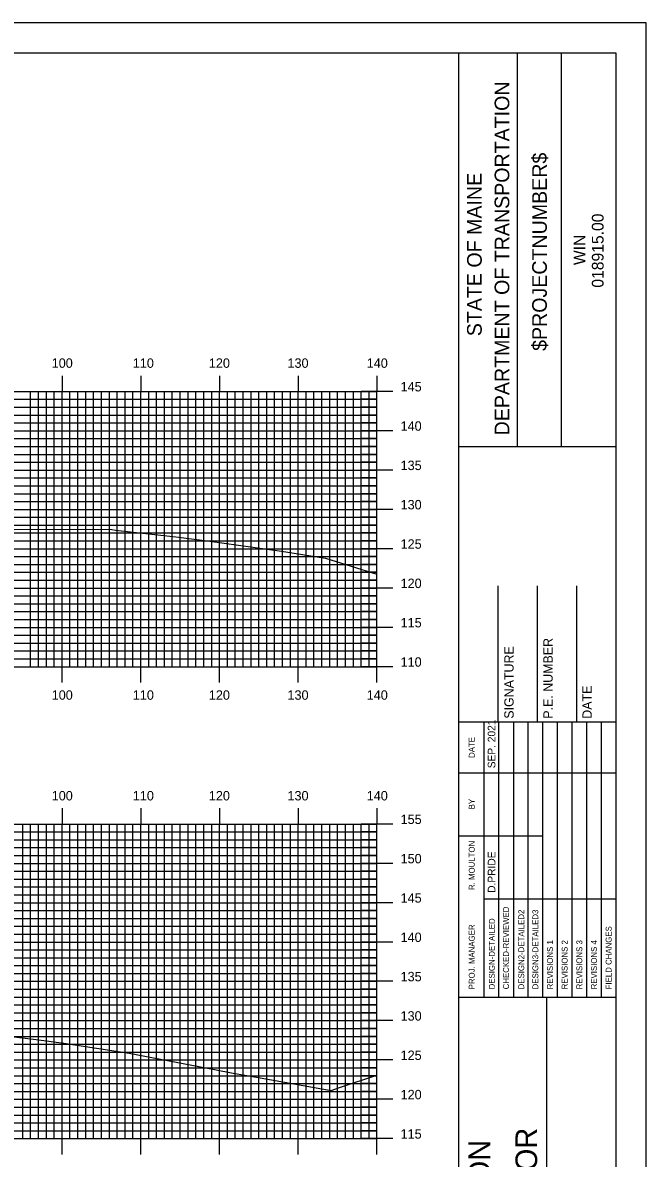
# Model space of a CAD drawing. Extents: x 852320 to 852663, y 366605 to 366825.
# Drawn here: x 852580.5 to 852659.7, y 366680.6 to 366824.9 of the extents above; entities that cross this region are included whole.
import ezdxf

# ---------------------------------------------------------------- set-up
doc = ezdxf.new("R2010")
doc.units = 0
for name, color, linetype in [('BORDER', 7, 'Continuous'), ('H_V ANNOTATION', 7, 'Continuous'), ('MAJOR', 7, 'Continuous'), ('MINOR', 7, 'Continuous'), ('PLOT BOUNDARY', 7, 'Continuous'), ('S_Roadway_Centerline', 7, 'Continuous')]:
    doc.layers.add(name, color=color, linetype=linetype)

msp = doc.modelspace()

# ---------------------------------------------------------------- linework, layer by layer
at = {"layer": 'BORDER'}
for p, q in [((852635.88, 366611.06), (852635.88, 366821.06)), ((852643.33, 366771.05), (852643.33, 366821.05)), ((852648.92, 366771.05), (852648.92, 366821.05)), ((852635.88, 366771.04), (852655.88, 366771.04)), ((852640.88, 366736.06), (852640.88, 366753.36)), ((852645.88, 366736.06), (852645.88, 366753.36)), ((852650.88, 366736.06), (852650.88, 366753.36)), ((852635.88, 366736.06), (852655.88, 366736.06)), ((852635.88, 366701.06), (852655.88, 366701.06)), ((852647.06, 366631.06), (852647.06, 366701.06))]:
    msp.add_line(p, q, dxfattribs=at)
msp.add_lwpolyline([(852335.88, 366611.06), (852655.88, 366611.06), (852655.88, 366821.06), (852335.88, 366821.06)], close=True, dxfattribs=at)
for points in [[(852639.11, 366729.56), (852639.11, 366736.06)], [(852640.97, 366701.07), (852640.97, 366736.06)], [(852642.84, 366736.06), (852642.84, 366701.07)], [(852644.7, 366701.07), (852644.7, 366736.06)], [(852646.56, 366701.07), (852646.56, 366736.06)], [(852648.43, 366701.07), (852648.43, 366736.06)], [(852650.29, 366701.07), (852650.29, 366736.06)], [(852652.15, 366701.07), (852652.15, 366736.06)], [(852654.02, 366701.07), (852654.02, 366736.06)], [(852639.11, 366701.07), (852639.11, 366734.65)], [(852635.88, 366729.56), (852655.88, 366729.56)], [(852635.88, 366721.56), (852639.11, 366721.56)], [(852639.11, 366721.56), (852646.56, 366721.56)], [(852639.11, 366713.56), (852655.88, 366713.56)]]:
    msp.add_lwpolyline(points, dxfattribs=at)
at = {"layer": 'MAJOR'}
for p, q in [((852585.48, 366780.06), (852585.48, 366778.06)), ((852595.48, 366780.06), (852595.48, 366778.06)), ((852605.48, 366780.06), (852605.48, 366778.06)), ((852615.48, 366780.06), (852615.48, 366778.06)), ((852625.48, 366780.06), (852625.48, 366778.06)), ((852345.48, 366778.06), (852625.48, 366778.06)), ((852345.48, 366778.06), (852625.48, 366778.06)), ((852585.48, 366743.06), (852585.48, 366778.06)), ((852595.48, 366743.06), (852595.48, 366778.06)), ((852605.48, 366743.06), (852605.48, 366778.06)), ((852615.48, 366743.06), (852615.48, 366778.06)), ((852627.48, 366778.06), (852623.47, 366778.06)), ((852625.48, 366743.06), (852625.48, 366778.06)), ((852625.48, 366743.06), (852625.48, 366778.06)), ((852345.48, 366773.06), (852625.48, 366773.06)), ((852627.48, 366773.06), (852623.47, 366773.06)), ((852345.48, 366768.06), (852625.48, 366768.06)), ((852627.48, 366768.06), (852623.47, 366768.06)), ((852345.48, 366763.06), (852625.48, 366763.06)), ((852627.48, 366763.06), (852623.47, 366763.06)), ((852345.48, 366758.06), (852625.48, 366758.06)), ((852627.48, 366758.06), (852623.47, 366758.06)), ((852345.48, 366753.06), (852625.48, 366753.06)), ((852627.48, 366753.06), (852623.47, 366753.06)), ((852345.48, 366748.06), (852625.48, 366748.06)), ((852627.48, 366748.06), (852623.47, 366748.06)), ((852345.48, 366743.06), (852625.48, 366743.06)), ((852345.48, 366743.06), (852625.48, 366743.06)), ((852585.48, 366741.05), (852585.48, 366743.06)), ((852595.48, 366741.05), (852595.48, 366743.06)), ((852605.48, 366741.05), (852605.48, 366743.06)), ((852615.48, 366741.05), (852615.48, 366743.06)), ((852627.48, 366743.06), (852623.47, 366743.06)), ((852625.48, 366741.05), (852625.48, 366743.06)), ((852585.48, 366725.06), (852585.48, 366723.06)), ((852595.48, 366725.06), (852595.48, 366723.06)), ((852605.48, 366725.06), (852605.48, 366723.06)), ((852615.48, 366725.06), (852615.48, 366723.06)), ((852625.48, 366725.06), (852625.48, 366723.06)), ((852345.48, 366723.06), (852625.48, 366723.06)), ((852345.48, 366723.06), (852625.48, 366723.06)), ((852585.48, 366683.06), (852585.48, 366723.06)), ((852595.48, 366683.06), (852595.48, 366723.06)), ((852605.48, 366683.06), (852605.48, 366723.06)), ((852615.48, 366683.06), (852615.48, 366723.06)), ((852627.48, 366723.06), (852623.47, 366723.06)), ((852625.48, 366683.06), (852625.48, 366723.06)), ((852625.48, 366683.06), (852625.48, 366723.06)), ((852345.48, 366718.06), (852625.48, 366718.06)), ((852627.48, 366718.06), (852623.47, 366718.06)), ((852345.48, 366713.06), (852625.48, 366713.06)), ((852627.48, 366713.06), (852623.47, 366713.06)), ((852345.48, 366708.06), (852625.48, 366708.06)), ((852627.48, 366708.06), (852623.47, 366708.06)), ((852345.48, 366703.06), (852625.48, 366703.06)), ((852627.48, 366703.06), (852623.47, 366703.06)), ((852345.48, 366698.06), (852625.48, 366698.06)), ((852627.48, 366698.06), (852623.47, 366698.06)), ((852345.48, 366693.06), (852625.48, 366693.06)), ((852627.48, 366693.06), (852623.47, 366693.06)), ((852345.48, 366688.06), (852625.48, 366688.06)), ((852627.48, 366688.06), (852623.47, 366688.06)), ((852345.48, 366683.06), (852625.48, 366683.06)), ((852345.48, 366683.06), (852625.48, 366683.06)), ((852585.48, 366681.05), (852585.48, 366683.06)), ((852595.48, 366681.05), (852595.48, 366683.06)), ((852605.48, 366681.05), (852605.48, 366683.06)), ((852615.48, 366681.05), (852615.48, 366683.06)), ((852627.48, 366683.06), (852623.47, 366683.06)), ((852625.48, 366681.05), (852625.48, 366683.06))]:
    msp.add_line(p, q, dxfattribs=at)
at = {"layer": 'MINOR'}
for p, q in [((852345.48, 366777.06), (852625.48, 366777.06)), ((852581.48, 366743.06), (852581.48, 366778.06)), ((852582.48, 366743.06), (852582.48, 366778.06)), ((852583.48, 366743.06), (852583.48, 366778.06)), ((852584.48, 366743.06), (852584.48, 366778.06)), ((852586.48, 366743.06), (852586.48, 366778.06)), ((852587.48, 366743.06), (852587.48, 366778.06)), ((852588.48, 366743.06), (852588.48, 366778.06)), ((852589.48, 366743.06), (852589.48, 366778.06)), ((852590.48, 366743.06), (852590.48, 366778.06)), ((852591.48, 366743.06), (852591.48, 366778.06)), ((852592.48, 366743.06), (852592.48, 366778.06)), ((852593.48, 366743.06), (852593.48, 366778.06)), ((852594.48, 366743.06), (852594.48, 366778.06)), ((852596.48, 366743.06), (852596.48, 366778.06)), ((852597.48, 366743.06), (852597.48, 366778.06)), ((852598.48, 366743.06), (852598.48, 366778.06)), ((852599.48, 366743.06), (852599.48, 366778.06)), ((852600.48, 366743.06), (852600.48, 366778.06)), ((852601.48, 366743.06), (852601.48, 366778.06)), ((852602.48, 366743.06), (852602.48, 366778.06)), ((852603.48, 366743.06), (852603.48, 366778.06)), ((852604.48, 366743.06), (852604.48, 366778.06)), ((852606.48, 366743.06), (852606.48, 366778.06)), ((852607.48, 366743.06), (852607.48, 366778.06)), ((852608.48, 366743.06), (852608.48, 366778.06)), ((852609.48, 366743.06), (852609.48, 366778.06)), ((852610.48, 366743.06), (852610.48, 366778.06)), ((852611.48, 366743.06), (852611.48, 366778.06)), ((852612.48, 366743.06), (852612.48, 366778.06)), ((852613.48, 366743.06), (852613.48, 366778.06)), ((852614.48, 366743.06), (852614.48, 366778.06)), ((852616.48, 366743.06), (852616.48, 366778.06)), ((852617.48, 366743.06), (852617.48, 366778.06)), ((852618.48, 366743.06), (852618.48, 366778.06)), ((852619.48, 366743.06), (852619.48, 366778.06)), ((852620.48, 366743.06), (852620.48, 366778.06)), ((852621.48, 366743.06), (852621.48, 366778.06)), ((852622.48, 366743.06), (852622.48, 366778.06)), ((852625.48, 366777.06), (852623.47, 366777.06)), ((852623.48, 366743.06), (852623.48, 366778.06)), ((852624.48, 366743.06), (852624.48, 366778.06)), ((852345.48, 366776.06), (852625.48, 366776.06)), ((852625.48, 366776.06), (852623.47, 366776.06)), ((852345.48, 366775.06), (852625.48, 366775.06)), ((852345.48, 366774.06), (852625.48, 366774.06)), ((852625.48, 366775.06), (852623.47, 366775.06)), ((852625.48, 366774.06), (852623.47, 366774.06)), ((852345.48, 366772.06), (852625.48, 366772.06)), ((852625.48, 366772.06), (852623.47, 366772.06)), ((852345.48, 366771.06), (852625.48, 366771.06)), ((852345.48, 366770.06), (852625.48, 366770.06)), ((852625.48, 366771.06), (852623.47, 366771.06)), ((852625.48, 366770.06), (852623.47, 366770.06)), ((852345.48, 366769.06), (852625.48, 366769.06)), ((852625.48, 366769.06), (852623.47, 366769.06)), ((852345.48, 366767.06), (852625.48, 366767.06)), ((852625.48, 366767.06), (852623.47, 366767.06)), ((852345.48, 366766.06), (852625.48, 366766.06)), ((852625.48, 366766.06), (852623.47, 366766.06)), ((852345.48, 366765.06), (852625.48, 366765.06)), ((852345.48, 366764.06), (852625.48, 366764.06)), ((852625.48, 366765.06), (852623.47, 366765.06)), ((852625.48, 366764.06), (852623.47, 366764.06)), ((852345.48, 366762.06), (852625.48, 366762.06)), ((852345.48, 366761.06), (852625.48, 366761.06)), ((852625.48, 366762.06), (852623.47, 366762.06)), ((852625.48, 366761.06), (852623.47, 366761.06)), ((852345.48, 366760.06), (852625.48, 366760.06)), ((852625.48, 366760.06), (852623.47, 366760.06)), ((852345.48, 366759.06), (852625.48, 366759.06)), ((852625.48, 366759.06), (852623.47, 366759.06)), ((852345.48, 366757.06), (852625.48, 366757.06)), ((852625.48, 366757.06), (852623.47, 366757.06)), ((852345.48, 366756.06), (852625.48, 366756.06)), ((852625.48, 366756.06), (852623.47, 366756.06)), ((852345.48, 366755.06), (852625.48, 366755.06)), ((852345.48, 366754.06), (852625.48, 366754.06)), ((852625.48, 366755.06), (852623.47, 366755.06)), ((852625.48, 366754.06), (852623.47, 366754.06)), ((852345.48, 366752.06), (852625.48, 366752.06)), ((852345.48, 366751.06), (852625.48, 366751.06)), ((852625.48, 366752.06), (852623.47, 366752.06)), ((852625.48, 366751.06), (852623.47, 366751.06)), ((852345.48, 366750.06), (852625.48, 366750.06)), ((852625.48, 366750.06), (852623.47, 366750.06)), ((852345.48, 366749.06), (852625.48, 366749.06)), ((852625.48, 366749.06), (852623.47, 366749.06)), ((852345.48, 366747.06), (852625.48, 366747.06)), ((852625.48, 366747.06), (852623.47, 366747.06)), ((852345.48, 366746.06), (852625.48, 366746.06)), ((852625.48, 366746.06), (852623.47, 366746.06)), ((852345.48, 366745.06), (852625.48, 366745.06)), ((852345.48, 366744.06), (852625.48, 366744.06)), ((852625.48, 366745.06), (852623.47, 366745.06)), ((852625.48, 366744.06), (852623.47, 366744.06)), ((852345.48, 366722.06), (852625.48, 366722.06)), ((852580.48, 366683.06), (852580.48, 366723.06)), ((852581.48, 366683.06), (852581.48, 366723.06)), ((852582.48, 366683.06), (852582.48, 366723.06)), ((852583.48, 366683.06), (852583.48, 366723.06)), ((852584.48, 366683.06), (852584.48, 366723.06)), ((852586.48, 366683.06), (852586.48, 366723.06)), ((852587.48, 366683.06), (852587.48, 366723.06)), ((852588.48, 366683.06), (852588.48, 366723.06)), ((852589.48, 366683.06), (852589.48, 366723.06)), ((852590.48, 366683.06), (852590.48, 366723.06)), ((852591.48, 366683.06), (852591.48, 366723.06)), ((852592.48, 366683.06), (852592.48, 366723.06)), ((852593.48, 366683.06), (852593.48, 366723.06)), ((852594.48, 366683.06), (852594.48, 366723.06)), ((852596.48, 366683.06), (852596.48, 366723.06)), ((852597.48, 366683.06), (852597.48, 366723.06)), ((852598.48, 366683.06), (852598.48, 366723.06)), ((852599.48, 366683.06), (852599.48, 366723.06)), ((852600.48, 366683.06), (852600.48, 366723.06)), ((852601.48, 366683.06), (852601.48, 366723.06)), ((852602.48, 366683.06), (852602.48, 366723.06)), ((852603.48, 366683.06), (852603.48, 366723.06)), ((852604.48, 366683.06), (852604.48, 366723.06)), ((852606.48, 366683.06), (852606.48, 366723.06)), ((852607.48, 366683.06), (852607.48, 366723.06)), ((852608.48, 366683.06), (852608.48, 366723.06)), ((852609.48, 366683.06), (852609.48, 366723.06)), ((852610.48, 366683.06), (852610.48, 366723.06)), ((852611.48, 366683.06), (852611.48, 366723.06)), ((852612.48, 366683.06), (852612.48, 366723.06)), ((852613.48, 366683.06), (852613.48, 366723.06)), ((852614.48, 366683.06), (852614.48, 366723.06)), ((852616.48, 366683.06), (852616.48, 366723.06)), ((852617.48, 366683.06), (852617.48, 366723.06)), ((852618.48, 366683.06), (852618.48, 366723.06)), ((852619.48, 366683.06), (852619.48, 366723.06)), ((852620.48, 366683.06), (852620.48, 366723.06)), ((852621.48, 366683.06), (852621.48, 366723.06)), ((852622.48, 366683.06), (852622.48, 366723.06)), ((852625.48, 366722.06), (852623.47, 366722.06)), ((852623.48, 366683.06), (852623.48, 366723.06)), ((852624.48, 366683.06), (852624.48, 366723.06)), ((852345.48, 366721.06), (852625.48, 366721.06)), ((852625.48, 366721.06), (852623.47, 366721.06)), ((852345.48, 366720.06), (852625.48, 366720.06)), ((852625.48, 366720.06), (852623.47, 366720.06)), ((852345.48, 366719.06), (852625.48, 366719.06)), ((852625.48, 366719.06), (852623.47, 366719.06)), ((852345.48, 366717.06), (852625.48, 366717.06)), ((852625.48, 366717.06), (852623.47, 366717.06)), ((852345.48, 366716.06), (852625.48, 366716.06)), ((852345.48, 366715.06), (852625.48, 366715.06)), ((852625.48, 366716.06), (852623.47, 366716.06)), ((852625.48, 366715.06), (852623.47, 366715.06)), ((852345.48, 366714.06), (852625.48, 366714.06)), ((852625.48, 366714.06), (852623.47, 366714.06)), ((852345.48, 366712.06), (852625.48, 366712.06)), ((852625.48, 366712.06), (852623.47, 366712.06)), ((852345.48, 366711.06), (852625.48, 366711.06)), ((852625.48, 366711.06), (852623.47, 366711.06)), ((852345.48, 366710.06), (852625.48, 366710.06)), ((852345.48, 366709.06), (852625.48, 366709.06)), ((852625.48, 366710.06), (852623.47, 366710.06)), ((852625.48, 366709.06), (852623.47, 366709.06)), ((852345.48, 366707.06), (852625.48, 366707.06)), ((852625.48, 366707.06), (852623.47, 366707.06)), ((852345.48, 366706.06), (852625.48, 366706.06)), ((852345.48, 366705.06), (852625.48, 366705.06)), ((852625.48, 366706.06), (852623.47, 366706.06)), ((852625.48, 366705.06), (852623.47, 366705.06)), ((852345.48, 366704.06), (852625.48, 366704.06)), ((852625.48, 366704.06), (852623.47, 366704.06)), ((852345.48, 366702.06), (852625.48, 366702.06)), ((852625.48, 366702.06), (852623.47, 366702.06)), ((852345.48, 366701.06), (852625.48, 366701.06)), ((852625.48, 366701.06), (852623.47, 366701.06)), ((852345.48, 366700.06), (852625.48, 366700.06)), ((852345.48, 366699.06), (852625.48, 366699.06)), ((852625.48, 366700.06), (852623.47, 366700.06)), ((852625.48, 366699.06), (852623.47, 366699.06)), ((852345.48, 366697.06), (852625.48, 366697.06)), ((852345.48, 366696.06), (852625.48, 366696.06)), ((852625.48, 366697.06), (852623.47, 366697.06)), ((852625.48, 366696.06), (852623.47, 366696.06)), ((852345.48, 366695.06), (852625.48, 366695.06)), ((852625.48, 366695.06), (852623.47, 366695.06)), ((852345.48, 366694.06), (852625.48, 366694.06)), ((852625.48, 366694.06), (852623.47, 366694.06)), ((852345.48, 366692.06), (852625.48, 366692.06)), ((852625.48, 366692.06), (852623.47, 366692.06)), ((852345.48, 366691.06), (852625.48, 366691.06)), ((852625.48, 366691.06), (852623.47, 366691.06)), ((852345.48, 366690.06), (852625.48, 366690.06)), ((852345.48, 366689.06), (852625.48, 366689.06)), ((852625.48, 366690.06), (852623.47, 366690.06)), ((852625.48, 366689.06), (852623.47, 366689.06)), ((852345.48, 366687.06), (852625.48, 366687.06)), ((852345.48, 366686.06), (852625.48, 366686.06)), ((852625.48, 366687.06), (852623.47, 366687.06)), ((852625.48, 366686.06), (852623.47, 366686.06)), ((852345.48, 366685.06), (852625.48, 366685.06)), ((852625.48, 366685.06), (852623.47, 366685.06)), ((852345.48, 366684.06), (852625.48, 366684.06)), ((852625.48, 366684.06), (852623.47, 366684.06))]:
    msp.add_line(p, q, dxfattribs=at)
at = {"layer": 'PLOT BOUNDARY'}
msp.add_lwpolyline([(852319.69, 366604.94), (852659.69, 366604.94), (852659.69, 366824.94), (852319.69, 366824.94)], close=True, dxfattribs=at)
at = {"layer": 'S_Roadway_Centerline'}
for points in [[(852578.84, 366760.53), (852591.8, 366760.52), (852592.26, 366760.43), (852599.93, 366759.57), (852604.26, 366759.01), (852613.35, 366757.74), (852618.96, 366756.84), (852625.48, 366754.84)], [(852577.58, 366696.2), (852582.17, 366695.66), (852585.72, 366695.18), (852594.02, 366693.93), (852604.84, 366691.87), (852607.23, 366691.37), (852610.19, 366690.86), (852619.65, 366689.19), (852620.85, 366689.6), (852625.48, 366691.14)]]:
    msp.add_lwpolyline(points, dxfattribs=at)

# ---------------------------------------------------------------- texts
at = {"layer": 'BORDER'}
for s, height, p in [('DEPARTMENT OF TRANSPORTATION', 1.8635, (852642.29, 366772.47)), ('$PROJECTNUMBER$', 1.8635, (852647.06, 366783.21)), ('STATE OF MAINE', 1.8635, (852638.79, 366785.08)), ('018915.00', 1.491, (852654.27, 366791.25)), ('WIN', 1.491, (852651.95, 366794.12)), ('P.E. NUMBER', 1.1811, (852647.8, 366736.45)), ('SIGNATURE', 1.181, (852642.84, 366736.45)), ('DATE', 1.181, (852652.76, 366736.45)), ('SEP. 2021', 0.969, (852640.52, 366730.15)), ('DATE', 0.743, (852637.89, 366731.47)), ('BY', 0.743, (852637.89, 366724.93)), ('R. MOULTON', 0.745, (852637.89, 366714.67)), ('D.PRIDE', 0.969, (852640.52, 366714.31)), ('CHECKED-REVIEWED', 0.7455, (852642.24, 366702.04)), ('DESIGN2-DETAILED2', 0.7455, (852644.18, 366702.04)), ('DESIGN3-DETAILED3', 0.7455, (852645.97, 366702.04)), ('DESIGN-DETAILED', 0.7455, (852640.45, 366702.04)), ('PROJ. MANAGER', 0.7455, (852637.89, 366702.04)), ('FIELD CHANGES', 0.7455, (852655.28, 366702.04)), ('REVISIONS 1', 0.7455, (852647.83, 366702.04)), ('REVISIONS 2', 0.7455, (852649.69, 366702.04)), ('REVISIONS 3', 0.7455, (852651.56, 366702.04)), ('REVISIONS 4', 0.7455, (852653.42, 366702.04)), ('1-395/ROUTE 9 CONNECTOR', 2.7557, (852645.83, 366633.26)), ('BREWER TO EDDINGTON', 2.7557, (852639.86, 366637.46))]:
    msp.add_text(s, height=height, rotation=90, dxfattribs=at).set_placement(p)
at = {"layer": 'H_V ANNOTATION'}
for s, p in [('100', (852584.16, 366781.06)), ('110', (852594.46, 366781.06)), ('120', (852604.12, 366781.06)), ('130', (852614.11, 366781.06)), ('140', (852624.18, 366781.06)), ('145', (852628.48, 366778.06)), ('140', (852628.48, 366773.06)), ('135', (852628.48, 366768.06)), ('130', (852628.48, 366763.06)), ('125', (852628.48, 366758.06)), ('120', (852628.48, 366753.06)), ('115', (852628.48, 366748.06)), ('110', (852628.48, 366743.06)), ('100', (852584.16, 366738.86)), ('110', (852594.46, 366738.86)), ('120', (852604.12, 366738.86)), ('130', (852614.11, 366738.86)), ('140', (852624.18, 366738.86)), ('100', (852584.16, 366726.06)), ('110', (852594.46, 366726.06)), ('120', (852604.12, 366726.06)), ('130', (852614.11, 366726.06)), ('140', (852624.18, 366726.06)), ('155', (852628.48, 366723.06)), ('150', (852628.48, 366718.06)), ('145', (852628.48, 366713.06)), ('140', (852628.48, 366708.06)), ('135', (852628.48, 366703.06)), ('130', (852628.48, 366698.06)), ('125', (852628.48, 366693.06)), ('120', (852628.48, 366688.06)), ('115', (852628.48, 366683.06))]:
    msp.add_text(s, height=1.2, dxfattribs=at).set_placement(p)

doc.saveas('drawing.dxf')
